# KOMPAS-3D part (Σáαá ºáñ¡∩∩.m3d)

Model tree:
1. Эскиз:1
2. Операция выдавливания:1
     Расстояние 1 = 1; Расстояние 2 = 6
3. Скругление:1
     Радиус = 5
4. Эскиз:2
5. Операция выдавливания:2
     Расстояние 1 = 1; Расстояние 2 = 2
6. Эскиз:3
7. Вырезать элемент выдавливания:1
     Расстояние 1 = 0.1
8. Плоскость, касательная в точке:1
9. Эскиз:4
10. Операция выдавливания:3
     Расстояние 1 = 1; Расстояние 2 = 2
11. Эскиз:5
12. Вырезать элемент выдавливания:2
     Расстояние 1 = 8
13. Эскиз:6
14. Операция выдавливания:4
     Расстояние 1 = 0.7; Расстояние 2 = 2
15. Эскиз:7
16. Операция выдавливания:5
     Расстояние 1 = 0.7; Расстояние 2 = 1
17. Эскиз:9
18. Вырезать элемент выдавливания:3
     Расстояние 1 = 3.08889
19. Скругление:3
     Радиус = 0.2
20. Эскиз:10
21. Операция выдавливания:6
     Расстояние 1 = 0.8; Расстояние 2 = 1
22. Эскиз:11
23. Операция выдавливания:7
     Расстояние 1 = 1.8; Расстояние 2 = 1
24. Эскиз:12
25. Операция выдавливания:8
     Расстояние 1 = 1; Расстояние 2 = 1
26. Эскиз:13
27. Операция выдавливания:9
     Расстояние 1 = 0.1; Расстояние 2 = 1.3
28. Эскиз:14
29. Операция выдавливания:10
     Расстояние 1 = 0.2; Расстояние 2 = 1.3
30. Эскиз:15
31. Операция выдавливания:11
     Расстояние 1 = 0.1; Расстояние 2 = 1.3
32. Скругление:4
     Радиус = 0.1
33. Массив по концентрической сетке:1  (with: Операция выдавливания:11, Скругление:4)  (labels: Экземпляр ( 1, 1 ); Экземпляр ( 1, 2 ); Экземпляр ( 1, 3 ); Экземпляр ( 1, 4 ))
     N 2 = 5; Шаг 2 = 360; Номер 2 = 1
34. Массив по концентрической сетке:2  (with: Операция выдавливания:3, Вырезать элемент выдавливания:2, Операция выдавливания:4, Операция выдавливания:5, Вырезать элемент выдавливания:3, Скругление:3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)  (labels: Экземпляр ( 1, 1 ); Экземпляр ( 1, 2 ); Экземпляр ( 1, 3 ); Экземпляр ( 1, 4 ))
     N 2 = 4; Шаг 2 = 360; Номер 2 = 1
35. Эскиз:16
36. Операция выдавливания:12
     Расстояние 1 = 0.1; Расстояние 2 = 5
37. Скругление:6
     Радиус = 0.3
38. Эскиз:17
39. Вырезать элемент выдавливания:4
     Расстояние 1 = 2
40. Эскиз:18
41. Операция выдавливания:13
     Расстояние 1 = 0.1; Расстояние 2 = 2
42. Эскиз:19
43. Операция выдавливания:14
     Расстояние 1 = 0.1; Расстояние 2 = 2
44. Эскиз:20
45. Операция выдавливания:15
     Расстояние 1 = 0.1; Расстояние 2 = 2
46. Эскиз:21
47. Операция выдавливания:16
     Расстояние 1 = 0.3; Расстояние 2 = 2
48. Скругление:7
     Радиус = 0.2

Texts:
  stalker61
  Сплав АЛ8  ГОСТ 1583-93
